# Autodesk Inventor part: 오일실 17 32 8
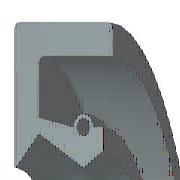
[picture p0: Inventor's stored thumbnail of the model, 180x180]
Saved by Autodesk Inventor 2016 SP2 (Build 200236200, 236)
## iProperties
IsCustomPart: 1
Created: 2012-02
Part Number: 오일실 17 32 8
Material: 고무
Description: 오일-실
Document SubType Name: Modeling
Standard: KS B 2804
Designer: mduedu
Standards Organization: KS
Language: ko-KR
Size Designation: D - 17 32 8
Categories: <MemberInstance><Categories><Category DisplayName="샤프트 부품" InternalName="7f7aeb1f-a693-4053-b835-cee3144e0d98" Mnemonic="SHFT"><Category DisplayName="실링" Intern
Density: 0.93 g/cm^3
Appearance: 고무 - 검은색 - 버전 1.1
Author: mduedu
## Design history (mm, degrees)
revolve "본체" stored, may be unused: angle "d17" = 90 deg
revolve "스프링1" stored, may be unused: angle "d18" = 90 deg
body "Solid1"
sketch "스케치1"
  geometry: L1 (0, 16)-(8, 16); L2 (8, 14.25)-(1.75, 14.25); L3 (1.75, 10.25)-(4.9, 8.5); L4 (4.9, 8.5)-(0, 8.5); L5 (0, 0)-(9.586, 0) reference; L6 (4.9, 8.5)-(6.3, 9.375); L7 (0, 18)-(0, -3) reference; L8 (-1.941, 0)-(11.507, 0) reference; L9 (4.2, 10.6)-(1.75, 11.21); L10 (1.75, 11.21)-(1.75, 14.25); L11 (0, 16)-(0, 8.588); L12 (4.9, 8.5)-(0, 8.5); L13 (1.75, 10.25)-(0.152, 8.528); L14 (8, 16)-(8, 14.25); L15 (5.6, 10.6)-(6.3, 10.6); L16 (6.3, 10.6)-(6.3, 9.375); C1 r 0.455 at (4.9, 10.6); A1 r 0.7 centre (4.9, 10.6) between (5.6, 10.6) and (4.2, 10.6); A2 r 0.088 centre (0.088, 8.588) between (0, 8.588) and (0.152, 8.528); 1 further point
  constraints: 28 end point, 5 horizontal alignment, 5 point on line, 4 point on circle, 4 vertical alignment, 3 centre point, 3 tangent, 2 collinear, 2 horizontal, 2 perpendicular, 1 coincident, 1 parallel
  dimensions: "d0" = 32 diameter of L1 L5 (= SD2); "d1" = 1.75 distance of L1.end L2.start (= SD); "d2" = 0.91 diameter of C1 (= SPDI); "d3" = 1.4 diameter of A1 (= SPDA); "d4" = 17 diameter of L3.end L5 (= NND); "d5" = 20.5 diameter of L3.start L5 (= TKDM); "d7" = 22.42 diameter of L9.end L5 (= TKDM + 0.24 x SWDT); "d8" = 1.75 distance between parallel lines of L11 L10 (= SD); "d9" = 4.9 distance from line of L11 C1.centre (= SPDST); "d10" = 21.2 diameter of C1.centre L5 (= HLDM); "d11" = 0.0875 radius of A2 (= 0.25 x LAB); "d12" = 6.3 distance between parallel lines of L11 L16 (= SDI); "d13" = 18.75 diameter of L6.end L5 (= ABDM); "d14" = 8 distance from line of L11 L1.end (= SWDT)
fillet "모깎기1" dims "d6" = 0.3 (= RR)
other parameters: "SD2" = 32 [user parameter; used in 1 equation term], "SWDT" = 8 [user parameter; used in 2 equation terms], "RR" = 0.3 [user parameter; used in 1 equation term], "SD" = 1.75 [user parameter; used in 2 equation terms], "NND" = 17 [user parameter; used in 1 equation term], "SPDA" = 1.4 [user parameter; used in 1 equation term], "SPDI" = 0.91 [user parameter; used in 1 equation term], "TKDM" = 20.5 [user parameter; used in 2 equation terms], "HLDM" = 21.2 [user parameter; used in 1 equation term], "ABDM" = 18.75 [user parameter; used in 1 equation term], "SDI" = 6.3 [user parameter; used in 1 equation term], "SPDST" = 4.9 [user parameter; used in 1 equation term], "LAB" = 0.35 [user parameter; used in 1 equation term], "d15" = 0, "d16" = 0, "d19" = 0
